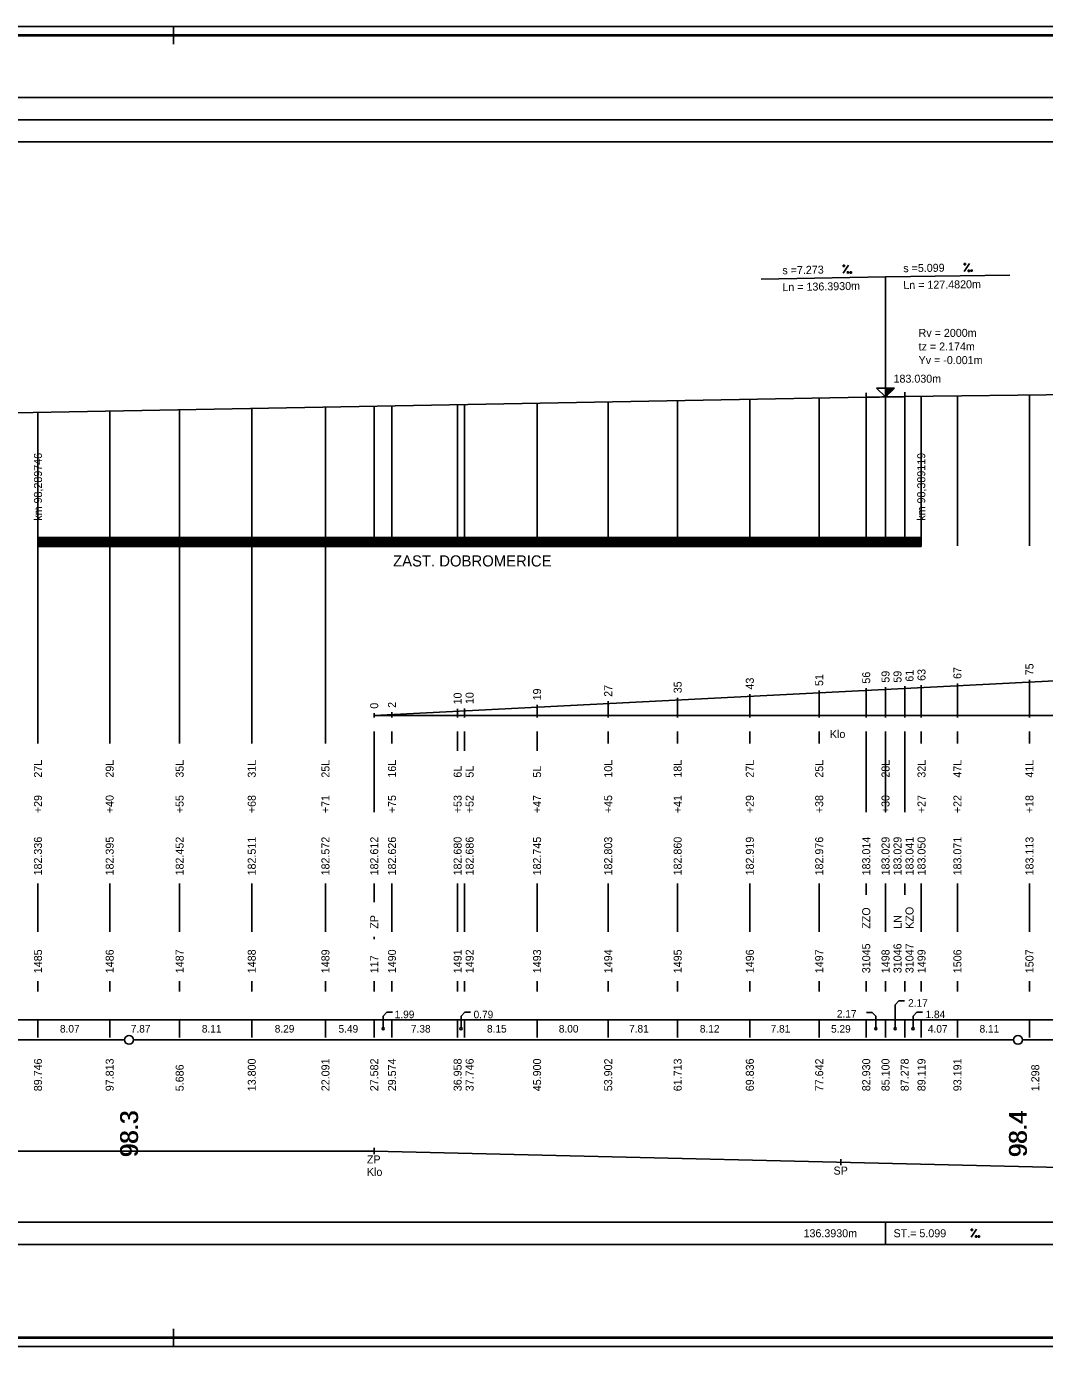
# Model space of a CAD drawing. Extents: x 0 to 10087, y -805 to 297.
# Drawn here: x 3956.9 to 4186, y 0 to 297 of the extents above; entities that cross this region are included whole.
import ezdxf

# ---------------------------------------------------------------- set-up
doc = ezdxf.new("R2010")
doc.units = 0
for name, color, linetype in [('CARKY_HODNOT', 7, 'Continuous'), ('KRIV1_CARA', 7, 'Continuous'), ('KRIV1_TEXT', 7, 'Continuous'), ('L_OBJEKTY_TEXT', 7, 'Continuous'), ('L_OBJEKTY_TVAR', 7, 'Continuous'), ('NIVELETA_CARA', 7, 'Continuous'), ('NIVELETA_TEXT', 7, 'Continuous'), ('PREV_CARA', 7, 'Continuous'), ('PREV_TEXT', 7, 'Continuous'), ('RAM', 7, 'Continuous'), ('REZERVA', 7, 'Continuous'), ('STAN_CARA', 7, 'Continuous'), ('STAN_PAS', 7, 'Continuous'), ('STAN_TEXT', 7, 'Continuous'), ('TEXT', 7, 'Continuous'), ('TXT_C_BODU', 7, 'Continuous')]:
    doc.layers.add(name, color=color, linetype=linetype)

msp = doc.modelspace()

# ---------------------------------------------------------------- linework, layer by layer
at = {"layer": 'CARKY_HODNOT'}
for p, q in [((4166.38, 180.14), (4166.38, 213.86)), ((4182.6, 180.14), (4182.6, 214.06)), ((4007.6, 138.35), (4007.6, 211.06)), ((4024.18, 138.35), (4024.18, 211.36)), ((4035.16, 180.14), (4035.16, 211.56)), ((4039.15, 180.14), (4039.15, 211.63)), ((4053.92, 180.14), (4053.92, 211.9)), ((4055.49, 180.14), (4055.49, 211.93)), ((4071.8, 180.14), (4071.8, 212.22)), ((4087.8, 180.14), (4087.8, 212.52)), ((4103.43, 180.14), (4103.43, 212.8)), ((4119.67, 180.14), (4119.67, 213.09)), ((4135.28, 180.14), (4135.28, 213.38)), ((4145.86, 180.14), (4145.86, 213.57)), ((4150.2, 180.14), (4150.2, 213.64)), ((4150.21, 180.14), (4150.21, 213.64)), ((4154.56, 180.14), (4154.56, 213.71)), ((4158.24, 180.14), (4158.24, 213.75)), ((3959.49, 138.35), (3959.49, 210.18)), ((3975.63, 138.35), (3975.63, 210.48)), ((3991.37, 138.35), (3991.37, 210.76)), ((3959.49, 135.65), (3959.49, 138.35)), ((3975.63, 135.65), (3975.63, 138.35)), ((3991.37, 135.65), (3991.37, 138.35)), ((4007.6, 135.65), (4007.6, 138.35)), ((4024.18, 135.65), (4024.18, 138.35)), ((4035.16, 126.2), (4035.16, 138.35)), ((4039.15, 135.65), (4039.15, 138.35)), ((4053.92, 134), (4053.92, 138.35)), ((4055.49, 134), (4055.49, 138.35)), ((4071.8, 134), (4071.8, 138.35)), ((4087.8, 135.65), (4087.8, 138.35)), ((4103.43, 135.65), (4103.43, 138.35)), ((4119.67, 135.65), (4119.67, 138.35)), ((4135.28, 135.65), (4135.28, 138.35)), ((4145.86, 126.2), (4145.86, 138.35)), ((4150.2, 135.65), (4150.2, 138.35)), ((4150.21, 126.2), (4150.21, 138.35)), ((4154.56, 126.2), (4154.56, 138.35)), ((4158.24, 135.65), (4158.24, 138.35)), ((4166.38, 135.65), (4166.38, 138.35)), ((4182.6, 135.65), (4182.6, 138.35)), ((4035.16, 120.25), (4035.16, 126.2)), ((4145.86, 120.25), (4145.86, 126.2)), ((4150.21, 120.25), (4150.21, 126.2)), ((4154.56, 120.25), (4154.56, 126.2)), ((3959.49, 93.3), (3959.49, 104.2)), ((3975.63, 93.3), (3975.63, 104.2)), ((3991.37, 93.3), (3991.37, 104.2)), ((4007.6, 93.3), (4007.6, 104.2)), ((4024.18, 93.3), (4024.18, 104.2)), ((4035.16, 100), (4035.16, 104.2)), ((4039.15, 93.3), (4039.15, 104.2)), ((4053.92, 93.3), (4053.92, 104.2)), ((4055.49, 93.3), (4055.49, 104.2)), ((4071.8, 93.3), (4071.8, 104.2)), ((4087.8, 93.3), (4087.8, 104.2)), ((4103.43, 93.3), (4103.43, 104.2)), ((4119.67, 93.3), (4119.67, 104.2)), ((4135.28, 93.3), (4135.28, 104.2)), ((4145.86, 101.65), (4145.86, 104.2)), ((4150.2, 93.3), (4150.2, 104.2)), ((4150.21, 100), (4150.21, 104.2)), ((4154.56, 101.65), (4154.56, 104.2)), ((4158.24, 93.3), (4158.24, 104.2)), ((4166.38, 93.3), (4166.38, 104.2)), ((4182.6, 93.3), (4182.6, 104.2)), ((4035.16, 91.65), (4035.16, 92.2)), ((3959.49, 79.9), (3959.49, 82.2)), ((3975.63, 79.9), (3975.63, 82.2)), ((3991.37, 79.9), (3991.37, 82.2)), ((4007.6, 79.9), (4007.6, 82.2)), ((4024.18, 79.9), (4024.18, 82.2)), ((4035.16, 79.9), (4035.16, 82.2)), ((4039.15, 79.9), (4039.15, 82.2)), ((4053.92, 79.9), (4053.92, 82.2)), ((4055.49, 79.9), (4055.49, 82.2)), ((4071.8, 79.9), (4071.8, 82.2)), ((4087.8, 79.9), (4087.8, 82.2)), ((4103.43, 79.9), (4103.43, 82.2)), ((4119.67, 79.9), (4119.67, 82.2)), ((4135.28, 79.9), (4135.28, 82.2)), ((4145.86, 79.9), (4145.86, 82.2)), ((4150.2, 79.9), (4150.2, 82.2)), ((4150.21, 79.9), (4150.21, 82.2)), ((4154.56, 79.9), (4154.56, 82.2)), ((4158.24, 79.9), (4158.24, 82.2)), ((4166.38, 79.9), (4166.38, 82.2)), ((4182.6, 79.9), (4182.6, 82.2))]:
    msp.add_line(p, q, dxfattribs=at)
at = {"layer": 'KRIV1_CARA'}
for p, q in [((4035.16, 44), (4035.16, 44.7)), ((3580.41, 44), (4035.16, 44)), ((4035.16, 44), (4245.16, 39)), ((4035.16, 44), (4035.16, 43.3)), ((4140.16, 41.5), (4140.16, 42.2)), ((4140.16, 41.5), (4140.16, 40.8))]:
    msp.add_line(p, q, dxfattribs=at)
at = {"layer": 'L_OBJEKTY_TVAR'}
for p, q in [((3959.49, 180), (3959.49, 183)), ((3959.49, 182), (4158.24, 182)), ((3959.49, 181.9), (4158.24, 181.9)), ((3959.49, 181.8), (4158.24, 181.8)), ((3959.49, 181.7), (4158.24, 181.7)), ((3959.49, 181.6), (4158.24, 181.6)), ((3959.49, 181.5), (4158.24, 181.5)), ((3959.49, 181.4), (4158.24, 181.4)), ((3959.49, 181.3), (4158.24, 181.3)), ((3959.49, 181.2), (4158.24, 181.2)), ((4158.24, 180), (4158.24, 183)), ((3959.49, 181.1), (4158.24, 181.1)), ((3959.49, 181), (4158.24, 181)), ((3959.49, 180.9), (4158.24, 180.9)), ((3959.49, 180.8), (4158.24, 180.8)), ((3959.49, 180.7), (4158.24, 180.7)), ((3959.49, 180.6), (4158.24, 180.6)), ((3959.49, 180.5), (4158.24, 180.5)), ((3959.49, 180.4), (4158.24, 180.4)), ((3959.49, 180.3), (4158.24, 180.3)), ((3959.49, 180.2), (4158.24, 180.2)), ((3959.49, 180.1), (4158.24, 180.1)), ((3959.49, 180), (4158.24, 180))]:
    msp.add_line(p, q, dxfattribs=at)
at = {"layer": 'NIVELETA_CARA'}
for p, q in [((300, 281), (8321.33, 281)), ((300, 276), (8321.33, 276)), ((300, 271), (8321.33, 271)), ((4150.21, 240.65), (4122.21, 240.14)), ((4150.21, 240.65), (4178.21, 241.01)), ((4150.21, 213.65), (4150.21, 240.65)), ((4145.86, 213.57), (4145.86, 214.57)), ((4150.21, 213.65), (4148.21, 215.65)), ((4148.21, 215.65), (4152.21, 215.65)), ((4150.21, 213.65), (4150.21, 215.65)), ((4152.21, 215.65), (4150.21, 213.65)), ((4150.27, 213.72), (4150.27, 215.65)), ((4150.34, 213.78), (4150.34, 215.65)), ((4150.41, 213.85), (4150.41, 215.65)), ((4150.47, 213.92), (4150.47, 215.65)), ((4150.54, 213.98), (4150.54, 215.65)), ((4150.61, 214.05), (4150.61, 215.65)), ((4150.67, 214.12), (4150.67, 215.65)), ((4150.74, 214.18), (4150.74, 215.65)), ((4150.81, 214.25), (4150.81, 215.65)), ((4150.87, 214.32), (4150.87, 215.65)), ((4150.94, 214.38), (4150.94, 215.65)), ((4151.01, 214.45), (4151.01, 215.65)), ((4151.07, 214.52), (4151.07, 215.65)), ((4151.14, 214.58), (4151.14, 215.65)), ((4151.21, 214.65), (4151.21, 215.65)), ((4151.27, 214.72), (4151.27, 215.65)), ((4151.34, 214.78), (4151.34, 215.65)), ((4151.41, 214.85), (4151.41, 215.65)), ((4151.47, 214.92), (4151.47, 215.65)), ((4151.54, 214.98), (4151.54, 215.65)), ((4151.61, 215.05), (4151.61, 215.65)), ((4151.67, 215.12), (4151.67, 215.65)), ((4151.74, 215.18), (4151.74, 215.65)), ((4151.81, 215.25), (4151.81, 215.65)), ((4151.87, 215.32), (4151.87, 215.65)), ((4151.94, 215.38), (4151.94, 215.65)), ((4152.01, 215.45), (4152.01, 215.65)), ((4152.07, 215.52), (4152.07, 215.65)), ((4152.14, 215.58), (4152.14, 215.65)), ((4154.56, 213.71), (4393.13, 216.75)), ((4154.56, 213.71), (4154.56, 214.71)), ((3878.41, 208.71), (4145.86, 213.57)), ((4145.86, 213.57), (4150.21, 213.65)), ((4145.86, 213.57), (4146.36, 213.58)), ((4146.36, 213.58), (4146.86, 213.59)), ((4146.86, 213.59), (4147.36, 213.6)), ((4147.36, 213.6), (4147.86, 213.61)), ((4147.86, 213.61), (4148.36, 213.61)), ((4148.36, 213.61), (4148.86, 213.62)), ((4148.86, 213.62), (4149.36, 213.63)), ((4149.36, 213.63), (4149.86, 213.64)), ((4149.86, 213.64), (4150.21, 213.64)), ((4150.21, 213.65), (4154.56, 213.71)), ((4150.21, 213.64), (4150.71, 213.65)), ((4150.71, 213.65), (4151.21, 213.66)), ((4151.21, 213.66), (4151.71, 213.67)), ((4151.71, 213.67), (4152.21, 213.67)), ((4152.21, 213.67), (4152.71, 213.68)), ((4152.71, 213.68), (4153.21, 213.69)), ((4153.21, 213.69), (4153.71, 213.69)), ((4153.71, 213.69), (4154.21, 213.7)), ((4154.21, 213.7), (4154.56, 213.71)), ((500, 28), (8321.33, 28)), ((4150.21, 23), (4150.21, 28)), ((500, 23), (8321.33, 23))]:
    msp.add_line(p, q, dxfattribs=at)
at = {"layer": 'NIVELETA_TEXT'}
for p, q in [((4168.18, 243.68), (4167.89, 243.67)), ((4167.89, 243.67), (4167.89, 243.38)), ((4167.89, 243.67), (4167.89, 243.67)), ((4167.91, 241.88), (4169.08, 243.69)), ((4168.19, 243.38), (4168.18, 243.68)), ((4140.97, 243.28), (4140.68, 243.27)), ((4140.68, 243.27), (4140.68, 242.98)), ((4140.68, 243.27), (4140.68, 243.27)), ((4140.68, 242.98), (4140.98, 242.98)), ((4140.71, 241.48), (4141.86, 243.3)), ((4140.98, 242.98), (4140.97, 243.28)), ((4141.61, 241.79), (4141.62, 241.5)), ((4141.62, 241.79), (4141.61, 241.79)), ((4141.91, 241.8), (4141.62, 241.79)), ((4141.62, 241.5), (4141.91, 241.5)), ((4141.91, 241.5), (4141.91, 241.8)), ((4142.22, 241.8), (4142.23, 241.51)), ((4142.52, 241.81), (4142.23, 241.8)), ((4142.23, 241.8), (4142.23, 241.8)), ((4142.23, 241.51), (4142.53, 241.51)), ((4142.53, 241.51), (4142.52, 241.81)), ((4167.89, 243.38), (4168.19, 243.38)), ((4168.81, 242.19), (4168.82, 241.89)), ((4168.82, 242.19), (4168.81, 242.18)), ((4169.11, 242.19), (4168.82, 242.19)), ((4168.82, 241.89), (4169.12, 241.89)), ((4169.12, 241.89), (4169.11, 242.19)), ((4169.73, 242.2), (4169.43, 242.19)), ((4169.43, 242.19), (4169.43, 241.9)), ((4169.43, 242.19), (4169.43, 242.19)), ((4169.43, 241.9), (4169.73, 241.9)), ((4169.73, 241.9), (4169.73, 242.2)), ((4169.51, 24.6), (4170.7, 26.4)), ((4169.51, 26.4), (4169.51, 26.1)), ((4169.52, 26.4), (4169.51, 26.39)), ((4169.51, 26.1), (4169.81, 26.1)), ((4169.81, 26.4), (4169.52, 26.4)), ((4169.81, 26.1), (4169.81, 26.4)), ((4170.42, 24.9), (4170.42, 24.6)), ((4170.43, 24.9), (4170.42, 24.89)), ((4170.42, 24.6), (4170.72, 24.6)), ((4170.72, 24.9), (4170.43, 24.9)), ((4170.72, 24.6), (4170.72, 24.9)), ((4171.03, 24.9), (4171.03, 24.6)), ((4171.04, 24.9), (4171.03, 24.89)), ((4171.03, 24.6), (4171.33, 24.6)), ((4171.33, 24.9), (4171.04, 24.9)), ((4171.33, 24.6), (4171.33, 24.9))]:
    msp.add_line(p, q, dxfattribs=at)
at = {"layer": 'PREV_CARA'}
for q in [(4245.16, 152.7), (4245.16, 142)]:
    msp.add_line((4035.16, 142), q, dxfattribs=at)
at = {"layer": 'PREV_TEXT'}
for p, q in [((4154.56, 141.5), (4154.56, 148.58)), ((4158.24, 141.5), (4158.24, 148.77)), ((4166.38, 141.5), (4166.38, 149.19)), ((4182.6, 141.5), (4182.6, 150.01)), ((4103.43, 141.5), (4103.43, 145.98)), ((4119.67, 141.5), (4119.67, 146.81)), ((4135.28, 141.5), (4135.28, 147.6)), ((4145.86, 141.5), (4145.86, 148.14)), ((4150.2, 141.5), (4150.2, 148.36)), ((4150.21, 141.5), (4150.21, 148.36)), ((4039.15, 141.5), (4039.15, 142.7)), ((4053.92, 141.5), (4053.92, 143.46)), ((4055.49, 141.5), (4055.49, 143.54)), ((4071.8, 141.5), (4071.8, 144.37)), ((4087.8, 141.5), (4087.8, 145.18)), ((4035.16, 141.5), (4035.16, 142.5))]:
    msp.add_line(p, q, dxfattribs=at)
at = {"layer": 'RAM'}
for p, q in [((8636.33, 297), (0, 297)), ((3990, 293), (3990, 297)), ((8634.33, 295.1), (2, 295.1)), ((8634.33, 295), (2, 295)), ((8634.33, 294.9), (2, 294.9)), ((3990, 0), (3990, 4)), ((0, 0), (8636.33, 0)), ((2, 2.1), (8634.33, 2.1)), ((2, 2), (8634.33, 2)), ((2, 1.9), (8634.33, 1.9))]:
    msp.add_line(p, q, dxfattribs=at)
at = {"layer": 'REZERVA'}
for centre in [(3980, 69), (4180, 69)]:
    msp.add_circle(centre, 1, dxfattribs=at)
at = {"layer": 'STAN_CARA'}
for p, q in [((3781, 69), (3979, 69)), ((3981, 69), (4179, 69)), ((4181, 69), (4379, 69))]:
    msp.add_line(p, q, dxfattribs=at)
at = {"layer": 'STAN_PAS'}
for p, q in [((4152.38, 76.9), (4153.23, 77.75)), ((4153.23, 77.75), (4154.51, 77.75)), ((4037.16, 74.35), (4038.01, 75.2)), ((4037.16, 71.75), (4037.16, 74.35)), ((4038.01, 75.2), (4039.28, 75.2)), ((4054.7, 74.35), (4055.55, 75.2)), ((4054.7, 71.75), (4054.7, 74.35)), ((4055.55, 75.2), (4056.83, 75.2)), ((4147.18, 75.17), (4145.9, 75.17)), ((4148.03, 74.33), (4147.18, 75.17)), ((4148.03, 71.75), (4148.03, 74.33)), ((4152.38, 71.75), (4152.38, 76.9)), ((4156.4, 74.35), (4157.25, 75.2)), ((4156.4, 71.75), (4156.4, 74.35)), ((4157.25, 75.2), (4158.52, 75.2)), ((300, 73.5), (8321.33, 73.5)), ((3959.49, 69.5), (3959.49, 73.5)), ((3975.63, 69.5), (3975.63, 73.5)), ((3991.37, 69.5), (3991.37, 73.5)), ((4007.6, 69.5), (4007.6, 73.5)), ((4024.18, 69.5), (4024.18, 73.5)), ((4035.16, 69.5), (4035.16, 73.5)), ((4039.15, 69.5), (4039.15, 73.5)), ((4053.92, 69.5), (4053.92, 73.5)), ((4055.49, 69.5), (4055.49, 73.5)), ((4071.8, 69.5), (4071.8, 73.5)), ((4087.8, 69.5), (4087.8, 73.5)), ((4103.43, 69.5), (4103.43, 73.5)), ((4119.67, 69.5), (4119.67, 73.5)), ((4135.28, 69.5), (4135.28, 73.5)), ((4145.86, 69.5), (4145.86, 73.5)), ((4150.2, 69.5), (4150.2, 73.5)), ((4150.21, 69.5), (4150.21, 73.5)), ((4154.56, 69.5), (4154.56, 73.5)), ((4158.24, 69.5), (4158.24, 73.5)), ((4166.38, 69.5), (4166.38, 73.5)), ((4182.6, 69.5), (4182.6, 73.5))]:
    msp.add_line(p, q, dxfattribs=at)
for centre in [(4037.16, 71.5), (4054.7, 71.5), (4148.03, 71.5), (4152.38, 71.5), (4156.4, 71.5)]:
    msp.add_circle(centre, 0.25, dxfattribs=at)

# ---------------------------------------------------------------- texts
at = {"layer": 'KRIV1_TEXT'}
for s, p in [('ZP', (4033.51, 41.2)), ('Klo', (4033.51, 38.4)), ('SP', (4138.51, 38.7))]:
    msp.add_text(s, height=1.8, dxfattribs=at).set_placement(p)
at = {"layer": 'L_OBJEKTY_TEXT'}
for s, p in [('km 98,289746', (3960.39, 185.8)), ('km 98,389119', (4159.14, 185.8))]:
    msp.add_text(s, height=1.8, rotation=90, dxfattribs=at).set_placement(p)
msp.add_text('ZAST. DOBROMERICE', height=2.5, dxfattribs=at).set_placement((4039.39, 175.5))
at = {"layer": 'NIVELETA_TEXT'}
for s, rotation, p in [('s =5.099', 0.7303, (4154.21, 241.7)), ('s =7.273', 1.0417, (4127.01, 241.23)), ('Ln = 136.3930m', 1.0417, (4127.01, 237.43)), ('Ln = 127.4820m', 0.7303, (4154.21, 237.9))]:
    msp.add_text(s, height=1.8, rotation=rotation, dxfattribs=at).set_placement(p)
for s, p in [('Rv = 2000m', (4157.65, 227.15)), ('tz = 2.174m', (4157.65, 224.09)), ('Yv = -0.001m', (4157.65, 221.03)), ('183.030m', (4152.01, 216.85)), ('136.3930m', (4131.76, 24.6)), ('ST.= 5.099', (4152.01, 24.6))]:
    msp.add_text(s, height=1.8, dxfattribs=at).set_placement(p)
at = {"layer": 'PREV_TEXT'}
for s, p in [('56', (4146.76, 149.14)), ('59', (4151.1, 149.36)), ('59', (4153.8, 149.36)), ('61', (4156.5, 149.58)), ('63', (4159.2, 149.77)), ('67', (4167.28, 150.19)), ('75', (4183.5, 151.01)), ('27', (4088.7, 146.18)), ('35', (4104.33, 146.98)), ('43', (4120.57, 147.81)), ('51', (4136.18, 148.6)), ('10', (4054.82, 144.46)), ('10', (4057.52, 144.54)), ('19', (4072.7, 145.37)), ('0', (4036.06, 143.5)), ('2', (4040.05, 143.7))]:
    msp.add_text(s, height=1.8, rotation=90, dxfattribs=at).set_placement(p)
msp.add_text('Klo', height=1.8, dxfattribs=at).set_placement((4137.69, 136.9))
at = {"layer": 'STAN_TEXT'}
for s, p in [('2.17', (4155.29, 76.46)), ('1.99', (4039.77, 73.88)), ('0.79', (4057.52, 73.86)), ('2.17', (4139.26, 74.01)), ('1.84', (4159.21, 73.89)), ('8.07', (3964.44, 70.65)), ('7.87', (3980.38, 70.65)), ('8.11', (3996.37, 70.65)), ('8.29', (4012.77, 70.65)), ('5.49', (4027.13, 70.63)), ('7.38', (4043.42, 70.65)), ('8.15', (4060.53, 70.65)), ('8.00', (4076.69, 70.65)), ('7.81', (4092.5, 70.65)), ('8.12', (4108.43, 70.65)), ('7.81', (4124.36, 70.65)), ('5.29', (4137.95, 70.63)), ('4.07', (4159.74, 70.63)), ('8.11', (4171.37, 70.65))]:
    msp.add_text(s, height=1.7, dxfattribs=at).set_placement(p)
for s, height, p in [('89.746', 1.8, (3960.39, 57.45)), ('97.813', 1.8, (3976.53, 57.45)), ('5.686', 1.8, (3992.27, 57.45)), ('13.800', 1.8, (4008.5, 57.45)), ('22.091', 1.8, (4025.08, 57.45)), ('27.582', 1.8, (4036.06, 57.45)), ('29.574', 1.8, (4040.05, 57.45)), ('36.958', 1.8, (4054.82, 57.45)), ('37.746', 1.8, (4057.52, 57.45)), ('45.900', 1.8, (4072.7, 57.45)), ('53.902', 1.8, (4088.7, 57.45)), ('61.713', 1.8, (4104.33, 57.45)), ('69.836', 1.8, (4120.57, 57.45)), ('77.642', 1.8, (4136.18, 57.45)), ('82.930', 1.8, (4146.76, 57.45)), ('85.100', 1.8, (4151.1, 57.45)), ('87.278', 1.8, (4155.42, 57.45)), ('89.119', 1.8, (4159.2, 57.45)), ('93.191', 1.8, (4167.28, 57.45)), ('1.298', 1.8, (4184.8, 57.45)), ('    98.3', 4, (3982, 36.84)), ('    98.3', 4, (3982, 36.74)), ('    98.3', 4, (3982, 36.64)), ('    98.4', 4, (4182, 36.84)), ('    98.4', 4, (4182, 36.74)), ('    98.4', 4, (4182, 36.64))]:
    msp.add_text(s, height=height, rotation=90, dxfattribs=at).set_placement(p)
at = {"layer": 'TEXT'}
for s, p in [('27L', (3960.39, 128)), ('29L', (3976.53, 128)), ('35L', (3992.27, 128)), ('31L', (4008.5, 128)), ('25L', (4025.08, 128)), ('16L', (4040.05, 128)), ('10L', (4088.7, 128)), ('18L', (4104.33, 128)), ('27L', (4120.57, 128)), ('25L', (4136.18, 128)), ('28L', (4151.1, 128)), ('32L', (4159.2, 128)), ('47L', (4167.28, 128)), ('41L', (4183.5, 128)), ('6L', (4054.82, 128)), ('5L', (4057.52, 128)), ('5L', (4072.7, 128)), ('+29', (3960.39, 120)), ('+40', (3976.53, 120)), ('+55', (3992.27, 120)), ('+68', (4008.5, 120)), ('+71', (4025.08, 120)), ('+75', (4040.05, 120)), ('+53', (4054.82, 120)), ('+52', (4057.52, 120)), ('+47', (4072.7, 120)), ('+45', (4088.7, 120)), ('+41', (4104.33, 120)), ('+29', (4120.57, 120)), ('+38', (4136.18, 120)), ('+30', (4151.1, 120)), ('+27', (4159.2, 120)), ('+22', (4167.28, 120)), ('+18', (4183.5, 120)), ('182.336', (3960.39, 106)), ('182.395', (3976.53, 106)), ('182.452', (3992.27, 106)), ('182.511', (4008.5, 106)), ('182.572', (4025.08, 106)), ('182.612', (4036.06, 106)), ('182.626', (4040.05, 106)), ('182.680', (4054.82, 106)), ('182.686', (4057.52, 106)), ('182.745', (4072.7, 106)), ('182.803', (4088.7, 106)), ('182.860', (4104.33, 106)), ('182.919', (4120.57, 106)), ('182.976', (4136.18, 106)), ('183.014', (4146.76, 106)), ('183.029', (4151.1, 106)), ('183.029', (4153.8, 106)), ('183.041', (4156.5, 106)), ('183.050', (4159.2, 106)), ('183.071', (4167.28, 106)), ('183.113', (4183.5, 106)), ('ZZO', (4146.76, 94)), ('KZO', (4156.5, 94)), ('ZP', (4036.06, 94)), ('LN', (4153.8, 94))]:
    msp.add_text(s, height=1.8, rotation=90, dxfattribs=at).set_placement(p)
at = {"layer": 'TXT_C_BODU'}
for s, p in [('1485', (3960.39, 84)), ('1486', (3976.53, 84)), ('1487', (3992.27, 84)), ('1488', (4008.5, 84)), ('1489', (4025.08, 84)), ('1490', (4040.05, 84)), ('1491', (4054.82, 84)), ('1492', (4057.52, 84)), ('1493', (4072.7, 84)), ('1494', (4088.7, 84)), ('1495', (4104.33, 84)), ('1496', (4120.57, 84)), ('1497', (4136.18, 84)), ('31045', (4146.76, 84)), ('1498', (4151.1, 84)), ('31046', (4153.8, 84)), ('31047', (4156.5, 84)), ('1499', (4159.2, 84)), ('1506', (4167.28, 84)), ('1507', (4183.5, 84)), ('117', (4036.06, 84))]:
    msp.add_text(s, height=1.8, rotation=90, dxfattribs=at).set_placement(p)

doc.saveas('drawing.dxf')
